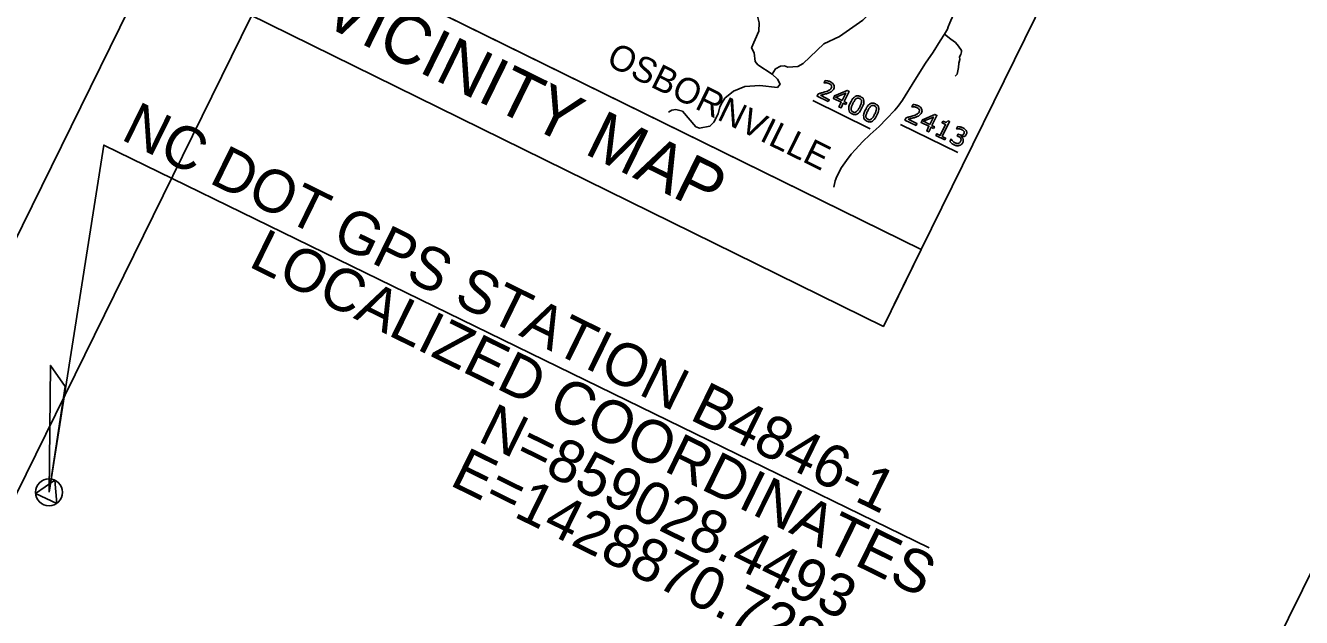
# Model space of a CAD drawing. Extents: x 1428428 to 1430511, y 857911 to 859585.
# Drawn here: x 1428861 to 1429385, y 858977 to 859220 of the extents above; entities that cross this region are included whole.
import ezdxf

# ---------------------------------------------------------------- set-up
doc = ezdxf.new("R2010")
doc.units = 0
for name, color, linetype in [('CTL NGS Horizontal CELL', 7, 'Continuous'), ('CTL Sheet Border CELL', 7, 'Continuous'), ('CTL Sheet Text', 7, 'Continuous'), ('Default', 7, 'Continuous'), ('Exist Hydrographic Creek Single Shore', 7, 'Continuous'), ('Exist Hydrographic Misc Water Feature', 7, 'Continuous'), ('Exist Road Non-System Type 51', 7, 'Continuous'), ('Exist Road Secondary Type 51 Attributed', 7, 'Continuous'), ('Scratch_Level_3', 7, 'Continuous'), ('Sheet Data Field CELL', 7, 'Continuous'), ('Sheet Title CELL', 7, 'Continuous')]:
    doc.layers.add(name, color=color, linetype=linetype)

# ---------------------------------------------------------------- blocks, each defined once
blk = doc.blocks.new('CTL NGS HORIZONTAL')
at = {"layer": 'CTL NGS Horizontal CELL'}
blk.add_line((0, 0), (0, 0), dxfattribs=at)
blk.add_lwpolyline([(-0.0638, -0.0372), (0.0638, -0.0372), (0, 0.0737), (-0.0638, -0.0372)], dxfattribs=at)
blk.add_circle((0, 0), 0.0738, dxfattribs=at)

msp = doc.modelspace()

# ---------------------------------------------------------------- linework, layer by layer
at = {"layer": 'CTL Sheet Border CELL'}
msp.add_lwpolyline([(1430484.04, 858893.65), (1429079.63, 859584.7), (1428595.9, 858601.62), (1430000.31, 857910.57)], close=True, dxfattribs=at)
at = {"layer": 'Default'}
for p, q in [((1429184.08, 859189.09), (1429207.65, 859177.49)), ((1429220.08, 859179.25), (1429243.56, 859167.7))]:
    msp.add_line(p, q, dxfattribs=at)
for points in [[(1429188.78, 859196.29), (1429188.74, 859196.31), (1429189.2, 859197.26)], [(1429197.61, 859187.46), (1429196.61, 859187.95), (1429195.68, 859186.06), (1429194.81, 859186.48), (1429195.74, 859188.38), (1429192.52, 859189.97), (1429193.03, 859191.01), (1429198.16, 859193.2), (1429198.99, 859192.79), (1429196.97, 859188.68), (1429197.97, 859188.19), (1429197.61, 859187.46)], [(1429196.1, 859189.11), (1429197.59, 859192.14), (1429193.49, 859190.39), (1429196.1, 859189.11)], [(1429190.42, 859188.64), (1429185.86, 859190.89), (1429186.33, 859191.84)], [(1429187.18, 859191.21), (1429190.81, 859189.42), (1429190.42, 859188.64)], [(1429224.78, 859186.45), (1429224.74, 859186.47), (1429225.21, 859187.42)], [(1429226.43, 859178.81), (1429221.87, 859181.05), (1429222.33, 859182)], [(1429233.61, 859177.62), (1429232.61, 859178.12), (1429231.68, 859176.22), (1429230.81, 859176.65), (1429231.74, 859178.54), (1429228.52, 859180.13), (1429229.03, 859181.17), (1429234.16, 859183.36), (1429234.99, 859182.95), (1429232.97, 859178.84), (1429233.97, 859178.35), (1429233.61, 859177.62)], [(1429232.1, 859179.27), (1429233.6, 859182.31), (1429229.49, 859180.55), (1429232.1, 859179.27)], [(1429223.19, 859181.37), (1429226.81, 859179.59), (1429226.43, 859178.81)], [(1429238.24, 859172.99), (1429234.6, 859174.78), (1429234.93, 859175.47), (1429236.34, 859174.78), (1429238.55, 859179.29), (1429237.15, 859179.98), (1429237.46, 859180.6)], [(1429239.49, 859180.76), (1429240.19, 859180.42), (1429237.2, 859174.35), (1429238.58, 859173.68), (1429238.24, 859172.99)], [(1429243.14, 859177.42), (1429243.09, 859177.44), (1429243.55, 859178.39)], [(1429240.33, 859172.31), (1429240.79, 859173.26), (1429240.86, 859173.22)], [(1429243.77, 859174.35), (1429243.36, 859174.55), (1429243.73, 859175.29), (1429244.04, 859175.14)], [(1429245, 859174.32), (1429244.97, 859174.25)], [(1428870.73, 859028.45), (1428893.19, 859170.83), (1429231.88, 859005.74)]]:
    msp.add_lwpolyline(points, dxfattribs=at)
msp.add_lwpolyline([(1428870.73, 859028.45), (1428871.27, 859080.45), (1428877.4, 859071.87)], close=True, dxfattribs=at)
for points in [[(1429189.2, 859197.26), (1429189.6, 859197.26), (1429190.2, 859197.12), (1429190.8, 859196.99), (1429191.31, 859196.74), (1429192.34, 859196.23), (1429192.69, 859195.45), (1429193.03, 859194.66), (1429192.61, 859193.8), (1429192.42, 859193.42), (1429192.16, 859193.14), (1429191.9, 859192.85), (1429191.56, 859192.65), (1429191.25, 859192.45), (1429190.88, 859192.3), (1429190.51, 859192.15), (1429190, 859191.98), (1429189.29, 859191.75), (1429188.55, 859191.56), (1429187.82, 859191.36), (1429187.18, 859191.21)], [(1429186.33, 859191.84), (1429187.01, 859192.01), (1429187.69, 859192.18), (1429188.36, 859192.35), (1429188.97, 859192.55), (1429190.26, 859192.96), (1429190.82, 859193.3), (1429191.39, 859193.64), (1429191.67, 859194.21), (1429191.93, 859194.73), (1429191.73, 859195.2), (1429191.52, 859195.67), (1429190.9, 859195.97), (1429190.49, 859196.18), (1429189.94, 859196.27), (1429189.39, 859196.36), (1429188.78, 859196.29)], [(1429204.27, 859186.02), (1429203.38, 859184.2), (1429202.39, 859183.63), (1429201.41, 859183.06), (1429200.21, 859183.65), (1429199, 859184.24), (1429198.87, 859185.38), (1429198.73, 859186.51), (1429199.61, 859188.3), (1429200.5, 859190.09), (1429201.48, 859190.67), (1429202.47, 859191.25), (1429203.67, 859190.66), (1429204.88, 859190.07), (1429205.01, 859188.92), (1429205.13, 859187.78), (1429204.27, 859186.02)], [(1429202.07, 859184.55), (1429202.41, 859184.83), (1429202.71, 859185.3), (1429203.01, 859185.77), (1429203.35, 859186.47), (1429203.69, 859187.15), (1429203.88, 859187.69), (1429204.08, 859188.22), (1429204.09, 859188.66), (1429204.1, 859189.08), (1429203.91, 859189.39), (1429203.73, 859189.7), (1429203.3, 859189.92), (1429202.87, 859190.12), (1429202.51, 859190.08), (1429202.14, 859190.05), (1429201.81, 859189.77), (1429201.49, 859189.51), (1429201.17, 859189), (1429200.84, 859188.49), (1429200.53, 859187.84), (1429200.18, 859187.14), (1429200, 859186.64), (1429199.81, 859186.14), (1429199.79, 859185.68), (1429199.77, 859185.26), (1429199.95, 859184.94), (1429200.13, 859184.62), (1429200.58, 859184.39), (1429201.01, 859184.19), (1429201.37, 859184.22), (1429201.74, 859184.26), (1429202.07, 859184.55)], [(1429210.37, 859183.01), (1429209.47, 859181.2), (1429208.49, 859180.63), (1429207.51, 859180.06), (1429206.31, 859180.65), (1429205.1, 859181.24), (1429204.97, 859182.38), (1429204.83, 859183.51), (1429205.71, 859185.29), (1429206.59, 859187.09), (1429207.58, 859187.67), (1429208.57, 859188.25), (1429209.76, 859187.66), (1429210.98, 859187.07), (1429211.1, 859185.92), (1429211.23, 859184.77), (1429210.37, 859183.01)], [(1429208.17, 859181.54), (1429208.51, 859181.83), (1429208.81, 859182.3), (1429209.11, 859182.77), (1429209.45, 859183.47), (1429209.79, 859184.15), (1429209.98, 859184.69), (1429210.17, 859185.22), (1429210.19, 859185.66), (1429210.2, 859186.08), (1429210.01, 859186.39), (1429209.83, 859186.7), (1429209.4, 859186.91), (1429208.97, 859187.12), (1429208.61, 859187.08), (1429208.24, 859187.04), (1429207.9, 859186.77), (1429207.59, 859186.51), (1429207.26, 859186), (1429206.94, 859185.49), (1429206.63, 859184.84), (1429206.28, 859184.14), (1429206.1, 859183.64), (1429205.91, 859183.14), (1429205.89, 859182.68), (1429205.86, 859182.26), (1429206.05, 859181.94), (1429206.23, 859181.62), (1429206.68, 859181.39), (1429207.1, 859181.19), (1429207.47, 859181.22), (1429207.84, 859181.26), (1429208.17, 859181.54)], [(1429225.21, 859187.42), (1429225.6, 859187.42), (1429226.21, 859187.29), (1429226.81, 859187.15), (1429227.31, 859186.91), (1429228.34, 859186.4), (1429228.69, 859185.61), (1429229.03, 859184.82), (1429228.61, 859183.97), (1429228.42, 859183.58), (1429228.16, 859183.3), (1429227.9, 859183.01), (1429227.56, 859182.81), (1429227.25, 859182.62), (1429226.88, 859182.46), (1429226.51, 859182.31), (1429226.01, 859182.15), (1429225.29, 859181.91), (1429224.55, 859181.72), (1429223.82, 859181.53), (1429223.19, 859181.37)], [(1429222.33, 859182), (1429223.01, 859182.17), (1429223.69, 859182.34), (1429224.37, 859182.52), (1429224.98, 859182.71), (1429226.26, 859183.13), (1429226.82, 859183.46), (1429227.39, 859183.8), (1429227.67, 859184.37), (1429227.93, 859184.9), (1429227.73, 859185.36), (1429227.53, 859185.83), (1429226.91, 859186.14), (1429226.49, 859186.34), (1429225.94, 859186.43), (1429225.39, 859186.52), (1429224.78, 859186.45)], [(1429237.46, 859180.6), (1429237.74, 859180.46), (1429238.09, 859180.34), (1429238.44, 859180.23), (1429238.65, 859180.24), (1429238.91, 859180.25), (1429239.12, 859180.36), (1429239.32, 859180.48), (1429239.49, 859180.76)], [(1429244.04, 859175.14), (1429244.73, 859174.8), (1429245.28, 859174.89), (1429245.83, 859174.97), (1429246.1, 859175.52), (1429246.22, 859175.77), (1429246.21, 859176), (1429246.2, 859176.24), (1429246.07, 859176.45), (1429245.93, 859176.66), (1429245.73, 859176.82), (1429245.53, 859176.97), (1429245.25, 859177.11), (1429244.82, 859177.32), (1429244.26, 859177.4), (1429243.7, 859177.49), (1429243.14, 859177.42)], [(1429243.55, 859178.39), (1429243.95, 859178.39), (1429244.56, 859178.25), (1429245.16, 859178.12), (1429245.66, 859177.88), (1429246.15, 859177.63), (1429246.48, 859177.36), (1429246.81, 859177.08), (1429247.02, 859176.74), (1429247.24, 859176.36), (1429247.25, 859175.97), (1429247.27, 859175.58), (1429247.07, 859175.17), (1429246.79, 859174.61), (1429246.19, 859174.38), (1429245.59, 859174.16), (1429245, 859174.32)], [(1429245.72, 859173.34), (1429245.84, 859173.04), (1429245.84, 859172.67), (1429245.83, 859172.31), (1429245.6, 859171.84), (1429245.38, 859171.38), (1429245.02, 859171.08), (1429244.66, 859170.78), (1429244.22, 859170.64), (1429243.73, 859170.49), (1429243.19, 859170.57), (1429242.66, 859170.64), (1429242.11, 859170.91), (1429241.55, 859171.18), (1429241.08, 859171.58), (1429240.6, 859171.98), (1429240.33, 859172.31)], [(1429240.86, 859173.22), (1429241.12, 859172.78), (1429241.56, 859172.36), (1429242, 859171.93), (1429242.48, 859171.7), (1429242.77, 859171.56), (1429243.13, 859171.49), (1429243.5, 859171.43), (1429243.79, 859171.52), (1429244.1, 859171.62), (1429244.32, 859171.81), (1429244.54, 859172), (1429244.72, 859172.36), (1429244.9, 859172.73), (1429244.9, 859173.02), (1429244.9, 859173.31), (1429244.76, 859173.55), (1429244.63, 859173.79), (1429244.37, 859173.99), (1429244.1, 859174.18), (1429243.77, 859174.35)], [(1429244.97, 859174.25), (1429245.16, 859174.11), (1429245.39, 859173.86), (1429245.61, 859173.6), (1429245.72, 859173.34)]]:
    msp.add_open_spline(points, degree=3, dxfattribs=at)
at = {"layer": 'Exist Hydrographic Creek Single Shore'}
for points in [[(1429167.35, 859199.95), (1429161.59, 859203.67), (1429160.48, 859205.14), (1429160.01, 859208.63), (1429158.99, 859210.63), (1429161.98, 859217.51), (1429162.03, 859220.88), (1429161.44, 859223.64)], [(1429146.94, 859188.21), (1429147.98, 859190.02), (1429151.52, 859192.92), (1429156.24, 859194.76), (1429162.3, 859195.25), (1429169.57, 859194.44), (1429170.66, 859195.8), (1429169.62, 859197.81), (1429167.35, 859199.95)]]:
    msp.add_lwpolyline(points, dxfattribs=at)
at = {"layer": 'Exist Hydrographic Misc Water Feature'}
for points in [[(1429167.35, 859199.95), (1429168.85, 859202.13), (1429170.89, 859203.15), (1429172.46, 859203.3), (1429173.89, 859202.77), (1429177.99, 859203.09), (1429180.09, 859204.23), (1429188.61, 859212.38), (1429194.99, 859215.29), (1429204.63, 859221.98), (1429206.59, 859223.92), (1429212.53, 859227.8), (1429219.8, 859230.61), (1429223.81, 859233.64), (1429226.92, 859238.24), (1429230.66, 859246.57), (1429232.15, 859251.27)], [(1429137.64, 859177.74), (1429141.87, 859178.55), (1429143.44, 859180.17), (1429145.22, 859183.61), (1429145.98, 859186.54), (1429146.94, 859188.21)], [(1429124.94, 859184.35), (1429126.29, 859185.13), (1429127.93, 859185.39), (1429130.6, 859184.74), (1429136.12, 859178.34), (1429137.64, 859177.74)]]:
    msp.add_lwpolyline(points, dxfattribs=at)
at = {"layer": 'Exist Road Non-System Type 51'}
for points in [[(1429238.11, 859216.32), (1429240.67, 859214.29), (1429242.66, 859212.89)], [(1429242.66, 859212.89), (1429243.89, 859211.34), (1429245.1, 859209.64), (1429245.07, 859209.03), (1429244.78, 859208.01), (1429244.32, 859206.98), (1429244.35, 859205.86), (1429243.98, 859204.46), (1429243.92, 859202.65), (1429243.57, 859201.3), (1429243.29, 859199.86), (1429242.43, 859199.08)]]:
    msp.add_lwpolyline(points, dxfattribs=at)
at = {"layer": 'Exist Road Secondary Type 51 Attributed'}
for points in [[(1429211.26, 859178.44), (1429214.27, 859181.53), (1429217.69, 859185.07), (1429219.11, 859186.83), (1429220.86, 859189.27), (1429225.99, 859197.44), (1429230.28, 859204.36), (1429233.41, 859208.93), (1429236.36, 859213.61), (1429238.11, 859216.32), (1429239.29, 859218.34), (1429239.68, 859219.31), (1429240.32, 859220.99), (1429241.66, 859224.11)], [(1429192.75, 859153.58), (1429193.27, 859156.09), (1429193.96, 859157.91), (1429195.92, 859161.55), (1429197.88, 859164.51), (1429199.83, 859167.02), (1429201.6, 859168.93), (1429204.53, 859172.09), (1429207.68, 859175.1), (1429211.26, 859178.44)]]:
    msp.add_lwpolyline(points, dxfattribs=at)
at = {"layer": 'Scratch_Level_3'}
for p, q in [((1429096.55, 859514.03), (1428739.64, 858788.69)), ((1429536.95, 859297.33), (1429180.04, 858571.98))]:
    msp.add_line(p, q, dxfattribs=at)
at = {"layer": 'Sheet Title CELL'}
for p, q in [((1429369.81, 859415.05), (1429228.53, 859127.93)), ((1429228.53, 859127.93), (1428950.38, 859264.79)), ((1429228.53, 859127.93), (1429217.49, 859105.49))]:
    msp.add_line(p, q, dxfattribs=at)
msp.add_lwpolyline([(1428950.38, 859264.79), (1429228.53, 859127.93), (1429213.05, 859096.45), (1428934.9, 859233.32)], close=True, dxfattribs=at)

# ---------------------------------------------------------------- block references
at = {"layer": 'CTL NGS Horizontal CELL', "xscale": 74.99999999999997, "yscale": 74.99999999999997, "rotation": -24.963754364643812}
msp.add_blockref('CTL NGS HORIZONTAL', (1428870.73, 859028.45), dxfattribs=at)

# ---------------------------------------------------------------- texts
at = {"layer": 'CTL Sheet Text'}
msp.add_text('2              GPS B4846-2         858534.9290     1429921.2587          1034.09         17+36.69         28.69 RT', height=6.25, rotation=333.8001, dxfattribs=at).set_placement((1429379.12, 859249.68))
at = {"layer": 'Default'}
msp.add_text('OSBORNVILLE', height=10.5, rotation=333.8001, dxfattribs=at).set_placement((1429098.86, 859203.88))
at = {"layer": 'Sheet Data Field CELL'}
for s, height, p in [('VICINITY MAP', 20, (1428981.76, 859220.73)), ('NC DOT GPS STATION B4846-1', 17.5002, (1428899.73, 859173.33)), ('LOCALIZED COORDINATES', 17.5002, (1428952.11, 859121.25)), ('N=859028.4493', 17.5002, (1429046.11, 859049.68)), ('E=1428870.7282', 17.5002, (1429034.64, 859031.6))]:
    msp.add_text(s, height=height, rotation=333.8001, dxfattribs=at).set_placement(p)

doc.saveas('drawing.dxf')
